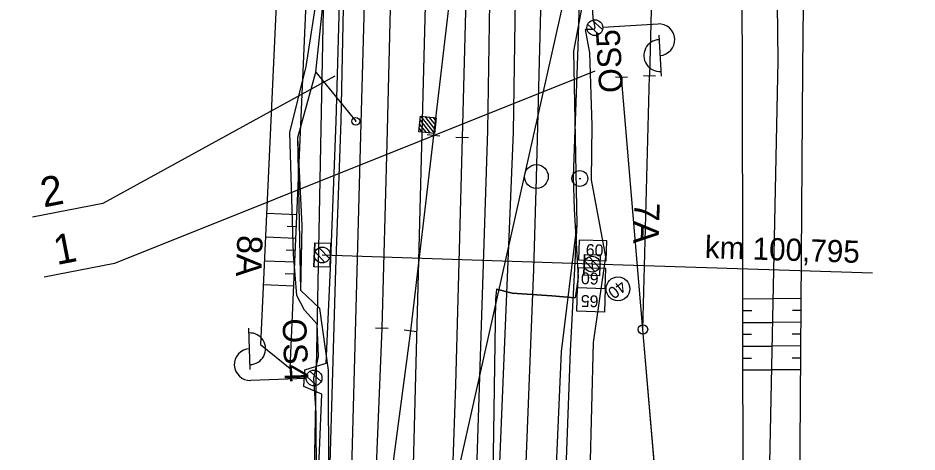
# Model space of a CAD drawing. Extents: x -545736 to -544888, y -1122892 to -1119128.
# Drawn here: x -545156.9 to -545100.2, y -1122572.7 to -1122545.3 of the extents above; entities that cross this region are included whole.
import ezdxf

# ---------------------------------------------------------------- set-up
doc = ezdxf.new("R2010")
doc.units = 0
for name, color, linetype in [('osvětlené plochy-hodnota-obrys', 7, 'Continuous'), ('so180602', 7, 'Continuous'), ('Vrstva 1', 7, 'Continuous'), ('Vrstva 1 - Koleje', 7, 'Continuous'), ('Vrstva 11 - Trakce', 7, 'Continuous'), ('Vrstva 12 - Trakce zaklady', 7, 'Continuous'), ('Vrstva 19 - Staniceni', 7, 'Continuous'), ('Vrstva 2', 7, 'Continuous'), ('Vrstva 2 - Vyhybky', 7, 'Continuous'), ('Vrstva 25', 7, 'Continuous'), ('Vrstva 26', 7, 'Continuous'), ('Vrstva 27', 7, 'Continuous'), ('Vrstva 28 - zabzar', 7, 'Continuous'), ('Vrstva 3 - Lisy - Pocitaci body', 7, 'Continuous'), ('Vrstva 31', 7, 'Continuous'), ('Vrstva 32', 7, 'Continuous'), ('Vrstva 35', 7, 'Continuous'), ('Vrstva 4 - Teren - stezky - prechody - plochy', 7, 'Continuous'), ('Vrstva 44', 7, 'Continuous'), ('Vrstva 48', 7, 'Continuous'), ('Vrstva 49', 7, 'Continuous'), ('Vrstva 5 - Vystroj', 7, 'Continuous'), ('Vrstva 63', 7, 'Continuous'), ('Vrstva 7 - Namezniky-vystroj', 7, 'Continuous')]:
    doc.layers.add(name, color=color, linetype=linetype)

msp = doc.modelspace()

# ---------------------------------------------------------------- linework, layer by layer
at = {"layer": 'osvětlené plochy-hodnota-obrys'}
for points in [[(-545134.488, -1122383.09), (-545138.436, -1122585.69), (-545142.696, -1122618.23), (-545150.566, -1122647.812), (-545144.37, -1122649.678)], [(-545136.491, -1122623.942), (-545134.432, -1122610.076), (-545134.432, -1122610.076), (-545130.588, -1122580.54), (-545121.507, -1122539.928), (-545114.985, -1122440.379), (-545107.655, -1122408.436), (-545092.05, -1122405.326)]]:
    msp.add_lwpolyline(points, dxfattribs=at)
at = {"layer": 'Vrstva 1'}
msp.add_line((-545117.455, -1122564.946), (-545117.039, -1122548.942), dxfattribs=at)
for points in [[(-545115.56, -1122488.812), (-545115.616, -1122491.209), (-545116.093, -1122511.333), (-545117.039, -1122548.942)], [(-545116.598, -1122574.975), (-545117.455, -1122564.946), (-545118.815, -1122549.016)]]:
    msp.add_lwpolyline(points, dxfattribs=at)
at = {"layer": 'Vrstva 1 - Koleje'}
for points in [[(-545127.491, -1122606.436), (-545126.409, -1122596.831), (-545125.507, -1122585.879), (-545124.881, -1122574.98), (-545124.42, -1122563.223), (-545124.354, -1122561.161), (-545124.185, -1122555.363), (-545123.884, -1122543.958), (-545123.736, -1122538.389), (-545123.69, -1122536.639), (-545123.368, -1122524.352), (-545123.06, -1122512.551), (-545122.825, -1122503.596), (-545122.749, -1122500.723), (-545122.248, -1122481.529), (-545122.227, -1122480.729)], [(-545132.113, -1122493.06), (-545132.351, -1122502.539), (-545132.576, -1122511.557), (-545132.791, -1122520.224), (-545133.022, -1122529.75), (-545133.182, -1122536.046), (-545133.362, -1122542.952), (-545133.631, -1122553.198), (-545133.835, -1122560.954), (-545133.937, -1122564.862), (-545134.77, -1122584.848), (-545135.963, -1122597.599), (-545136.038, -1122598.395)], [(-545128.351, -1122532.879), (-545128.372, -1122533.679), (-545128.87, -1122552.83), (-545129.057, -1122559.925), (-545129.288, -1122568.437), (-545129.604, -1122577.497), (-545129.925, -1122584.285), (-545130.831, -1122596.948), (-545132.201, -1122608.983), (-545133.84, -1122619.134), (-545136.174, -1122630.305), (-545137.455, -1122635.497), (-545140.817, -1122647.245), (-545144.325, -1122657.562), (-545148.206, -1122667.467), (-545152.577, -1122677.284), (-545157.303, -1122686.734), (-545161.121, -1122693.673), (-545165.852, -1122701.579), (-545166.19, -1122702.117), (-545166.476, -1122702.566), (-545172.093, -1122711.045)], [(-545128.351, -1122532.879), (-545128.444, -1122533.674), (-545130.677, -1122552.693), (-545132.131, -1122565.025), (-545134.77, -1122584.848), (-545135.963, -1122597.599), (-545136.038, -1122598.395)]]:
    msp.add_lwpolyline(points, dxfattribs=at)
at = {"layer": 'Vrstva 11 - Trakce'}
for p, q in [((-545137.534, -1122560.711), (-545138.158, -1122560.044)), ((-545137.255, -1122560.46), (-545137.888, -1122559.783)), ((-545120.658, -1122560.825), (-545137.702, -1122560.244)), ((-545120.489, -1122561.292), (-545121.114, -1122560.625)), ((-545120.211, -1122561.041), (-545120.844, -1122560.365))]:
    msp.add_line(p, q, dxfattribs=at)
for centre in [(-545137.702, -1122560.244), (-545120.658, -1122560.825)]:
    msp.add_circle(centre, 0.5, dxfattribs=at)
at = {"layer": 'Vrstva 12 - Trakce zaklady'}
for p, q in [((-545138.173, -1122559.467), (-545137.174, -1122559.501)), ((-545121.148, -1122560.204), (-545120.149, -1122560.237)), ((-545137.225, -1122561.014), (-545138.224, -1122560.98)), ((-545120.193, -1122561.56), (-545121.192, -1122561.527))]:
    msp.add_line(p, q, dxfattribs=at)
for points in [[(-545137.174, -1122559.501), (-545137.225, -1122561.014), (-545138.224, -1122560.98), (-545138.173, -1122559.467), (-545137.174, -1122559.501)], [(-545138.173, -1122559.467), (-545138.173, -1122559.467), (-545138.224, -1122560.98), (-545138.224, -1122560.98)], [(-545137.174, -1122559.501), (-545137.174, -1122559.501), (-545137.225, -1122561.014), (-545137.225, -1122561.014)], [(-545121.192, -1122561.527), (-545121.148, -1122560.204), (-545120.149, -1122560.237), (-545120.193, -1122561.56), (-545121.192, -1122561.527)], [(-545121.148, -1122560.204), (-545121.148, -1122560.204), (-545121.192, -1122561.527), (-545121.192, -1122561.527)], [(-545120.149, -1122560.237), (-545120.149, -1122560.237), (-545120.193, -1122561.56), (-545120.193, -1122561.56)]]:
    msp.add_lwpolyline(points, dxfattribs=at)
at = {"layer": 'Vrstva 19 - Staniceni'}
msp.add_circle((-545124.183, -1122555.287), 0.75, dxfattribs=at)
at = {"layer": 'Vrstva 2'}
for p, q in [((-545118.44, -1122549.026), (-545119.19, -1122549.006)), ((-545117.455, -1122564.946), (-545117.039, -1122548.942)), ((-545116.664, -1122548.952), (-545117.414, -1122548.932))]:
    msp.add_line(p, q, dxfattribs=at)
msp.add_lwpolyline([(-545116.598, -1122574.975), (-545116.655, -1122574.287), (-545117.455, -1122564.946), (-545118.815, -1122549.016)], dxfattribs=at)
msp.add_circle((-545117.455, -1122564.946), 0.3, dxfattribs=at)
at = {"layer": 'Vrstva 2 - Vyhybky'}
for p, q in [((-545130.28, -1122552.74), (-545131.074, -1122552.646)), ((-545128.47, -1122552.841), (-545129.27, -1122552.819)), ((-545134.337, -1122564.852), (-545133.537, -1122564.872)), ((-545132.528, -1122564.978), (-545131.734, -1122565.072))]:
    msp.add_line(p, q, dxfattribs=at)
for points in [[(-545126.015, -1122512.98), (-545128.258, -1122532.085), (-545128.351, -1122532.879), (-545128.444, -1122533.674), (-545130.677, -1122552.693)], [(-545127.83, -1122512.852), (-545128.33, -1122532.079), (-545128.351, -1122532.879), (-545128.372, -1122533.679), (-545128.87, -1122552.83)], [(-545132.131, -1122565.025), (-545134.77, -1122584.848), (-545135.963, -1122597.599), (-545136.038, -1122598.395)], [(-545133.937, -1122564.862), (-545134.77, -1122584.848)]]:
    msp.add_lwpolyline(points, dxfattribs=at)
at = {"layer": 'Vrstva 25'}
for p, q in [((-545120.945, -1122545.671), (-545120.23, -1122546.307)), ((-545120.669, -1122545.415), (-545120.011, -1122546)), ((-545119.996, -1122545.855), (-545116.502, -1122545.649)), ((-545116.461, -1122546.348), (-545116.308, -1122548.943)), ((-545142.244, -1122567.466), (-545142.342, -1122564.868)), ((-545138.72, -1122568.033), (-545142.217, -1122568.166)), ((-545138.056, -1122568.486), (-545138.701, -1122567.888)), ((-545137.774, -1122568.236), (-545138.476, -1122567.585))]:
    msp.add_line(p, q, dxfattribs=at)
for centre in [(-545120.495, -1122545.884), (-545120.495, -1122545.884), (-545138.22, -1122568.014), (-545138.22, -1122568.014)]:
    msp.add_circle(centre, 0.5, dxfattribs=at)
for centre, start, end in [((-545116.443, -1122546.647), 273.3665, 93.3665), ((-545116.397, -1122547.646), 92.6639, 274.069), ((-545142.281, -1122566.167), 271.4722, 92.8773), ((-545142.255, -1122567.167), 92.1747, 272.1747)]:
    msp.add_arc(centre, 1, start, end, dxfattribs=at)
at = {"layer": 'Vrstva 26'}
for points in [[(-545119.68, -1122488.49), (-545120.17, -1122501.15), (-545119.71, -1122502.33), (-545119.7, -1122504.78), (-545119.85, -1122506.31), (-545120.44, -1122510.12), (-545120.81, -1122524.13), (-545121.12, -1122536.77), (-545120.62, -1122545.27), (-545120.495, -1122545.884), (-545120.53, -1122546.01), (-545121.1, -1122546), (-545120.82, -1122547.48), (-545120.68, -1122552.06), (-545120.73, -1122555.49), (-545119.81, -1122560.36), (-545120.59, -1122565.76), (-545120.92, -1122578.15), (-545121.15, -1122584.54), (-545121.23, -1122585.48), (-545121.28, -1122585.86), (-545121.286, -1122586.03)], [(-545138.229, -1122568.031), (-545137.937, -1122566.657), (-545138.015, -1122564.603), (-545138.832, -1122563.727), (-545139.297, -1122562.807), (-545139.509, -1122560.192), (-545139.746, -1122552.512), (-545138.721, -1122548.343), (-545137.938, -1122543.312), (-545136.85, -1122534.793), (-545136.864, -1122531.996), (-545136.831, -1122528.647), (-545137.221, -1122526.243), (-545137.59, -1122523.973), (-545137.332, -1122522.241), (-545137.098, -1122519.747), (-545136.605, -1122518.752), (-545136.193, -1122512.982), (-545134.952, -1122511.155), (-545134.594, -1122508.496), (-545134.254, -1122496.631)], [(-545140.173, -1122601.416), (-545139.225, -1122598.674), (-545138.828, -1122595.457), (-545138.236, -1122588.391), (-545138.033, -1122583.268), (-545138.077, -1122570.236), (-545138.229, -1122568.031), (-545138.22, -1122568.014)]]:
    msp.add_lwpolyline(points, dxfattribs=at)
at = {"layer": 'Vrstva 27'}
msp.add_line((-545135.581, -1122551.825), (-545135.579, -1122551.775), dxfattribs=at)
msp.add_circle((-545135.58, -1122551.8), 0.25, dxfattribs=at)
at = {"layer": 'Vrstva 28 - zabzar'}
msp.add_line((-545138.1, -1122548.7), (-545135.58, -1122551.8), dxfattribs=at)
for points in [[(-545139.49, -1122604.09), (-545138.69, -1122597.74), (-545138.27, -1122594.46), (-545137.55, -1122584.26), (-545137.29, -1122574.56), (-545137.31, -1122567.52), (-545137.85, -1122563.63), (-545139.06, -1122562.49), (-545138.96, -1122558.39), (-545139.24, -1122552.83), (-545138.1, -1122548.7), (-545137.31, -1122541.08), (-545136.56, -1122536.26), (-545136.54, -1122531.79), (-545136.53, -1122525.43), (-545137.3, -1122521.01), (-545137.26, -1122503.3), (-545136.84, -1122494.09)], [(-545120.32, -1122497.45), (-545120.28, -1122501.2), (-545119.86, -1122502.26), (-545120.03, -1122503.25), (-545120.08, -1122505.06), (-545120.41, -1122515.25), (-545120.88, -1122524.03), (-545121.29, -1122538.53), (-545121.33, -1122539.85), (-545121.51, -1122544.9), (-545121.56, -1122547.09), (-545121.86, -1122555.28), (-545121.79, -1122557.35), (-545121.55, -1122561.65), (-545121.74, -1122562.94), (-545123.21, -1122562.82), (-545125.72, -1122562.65), (-545126.7, -1122562.41), (-545126.77, -1122563.06), (-545126.93, -1122574.21), (-545127.34, -1122580.8), (-545127.46, -1122581.87)]]:
    msp.add_lwpolyline(points, dxfattribs=at)
at = {"layer": 'Vrstva 3 - Lisy - Pocitaci body'}
for p, q in [((-545131.495, -1122551.467), (-545130.618, -1122552.577)), ((-545131.232, -1122551.498), (-545130.587, -1122552.313)), ((-545130.968, -1122551.529), (-545130.556, -1122552.05)), ((-545130.705, -1122551.56), (-545130.526, -1122551.787)), ((-545131.557, -1122551.994), (-545131.145, -1122552.515)), ((-545131.526, -1122551.73), (-545130.881, -1122552.546)), ((-545131.588, -1122552.257), (-545131.408, -1122552.484))]:
    msp.add_line(p, q, dxfattribs=at)
msp.add_lwpolyline([(-545130.502, -1122551.583), (-545130.618, -1122552.577), (-545131.611, -1122552.46), (-545131.495, -1122551.467)], close=True, dxfattribs=at)
at = {"layer": 'Vrstva 31'}
msp.add_lwpolyline([(-545139.49, -1122604.09), (-545138.69, -1122597.74), (-545138.27, -1122594.46), (-545137.55, -1122584.26), (-545137.29, -1122574.56), (-545137.31, -1122567.52), (-545137.85, -1122563.63), (-545139.06, -1122562.49), (-545139.24, -1122552.83), (-545138.1, -1122548.7), (-545137.31, -1122541.08), (-545136.56, -1122536.26), (-545136.53, -1122525.43), (-545137.3, -1122521.01), (-545137.26, -1122503.3), (-545136.84, -1122494.09)], dxfattribs=at)
at = {"layer": 'Vrstva 32'}
msp.add_lwpolyline([(-545139.49, -1122604.09), (-545138.2, -1122600.33), (-545138.01, -1122598.42), (-545138.69, -1122597.74), (-545138.27, -1122594.46), (-545137.55, -1122584.26), (-545137.29, -1122574.56), (-545137.31, -1122567.52), (-545137.85, -1122563.63), (-545139.06, -1122562.49), (-545138.96, -1122558.39), (-545139.24, -1122552.83), (-545138.1, -1122548.7), (-545137.31, -1122541.08), (-545136.56, -1122536.26), (-545136.53, -1122525.43), (-545137.3, -1122521.01), (-545137.26, -1122503.3), (-545136.84, -1122494.09)], dxfattribs=at)
msp.add_lwpolyline([(-545139.49, -1122604.09), (-545138.2, -1122600.33), (-545138.01, -1122598.42), (-545138.69, -1122597.74), (-545138.27, -1122594.46), (-545137.55, -1122584.26), (-545137.29, -1122574.56), (-545137.31, -1122567.52), (-545137.85, -1122563.63), (-545139.06, -1122562.49), (-545138.96, -1122558.39), (-545139.24, -1122552.83), (-545138.1, -1122548.7), (-545137.31, -1122541.08), (-545136.56, -1122536.26), (-545136.53, -1122525.43), (-545137.3, -1122521.01), (-545137.26, -1122503.3), (-545136.84, -1122494.09)], dxfattribs=at)
at = {"layer": 'Vrstva 35'}
msp.add_lwpolyline([(-545126.7, -1122562.41), (-545125.72, -1122562.65), (-545123.21, -1122562.82), (-545121.74, -1122562.94)], dxfattribs=at)
at = {"layer": 'Vrstva 4 - Teren - stezky - prechody - plochy'}
for points in [[(-545191.629, -1122723.588), (-545190.606, -1122724.4), (-545183.082, -1122715.247), (-545174.471, -1122703.078), (-545169.188, -1122694.668), (-545163.388, -1122684.3), (-545157.763, -1122672.946), (-545152.235, -1122660.118), (-545147.809, -1122647.698), (-545144.117, -1122635.247), (-545141.561, -1122624.265), (-545139.354, -1122611.942), (-545137.55, -1122598.304), (-545138.381, -1122598.177), (-545138.144, -1122596.165), (-545137.394, -1122596.23), (-545137.164, -1122594.37), (-545136.011, -1122579.974), (-545135.245, -1122551.924), (-545134.376, -1122521.14), (-545133.892, -1122501.709), (-545133.405, -1122481.658)], [(-545140.685, -1122611.253), (-545138.752, -1122594.386), (-545137.402, -1122579.893), (-545136.844, -1122561.129), (-545136.511, -1122551.767), (-545135.87, -1122521.211), (-545135.812, -1122519.734), (-545135.589, -1122501.439), (-545134.927, -1122481.492), (-545133.405, -1122481.658)], [(-545126.359, -1122615.637), (-545123.475, -1122595.334), (-545122.576, -1122581.189), (-545122.024, -1122566.306), (-545121.598, -1122558.297), (-545121.821, -1122547.368), (-545120.582, -1122540.764), (-545120.053, -1122538.008), (-545120.048, -1122536.451), (-545120.424, -1122535.984), (-545120.015, -1122521.738), (-545120.268, -1122521.539), (-545120.287, -1122519.886), (-545120.045, -1122519.696), (-545119.214, -1122493.259)], [(-545141.024, -1122611.09), (-545139.933, -1122602.085), (-545139.716, -1122601.069), (-545140.128, -1122600.945), (-545139.688, -1122595.933), (-545139.138, -1122595.855), (-545139.019, -1122594.44), (-545139.197, -1122594.314), (-545138.162, -1122579.754), (-545137.734, -1122569.04), (-545138.855, -1122568.556), (-545138.807, -1122567.496), (-545137.462, -1122567.077), (-545137.179, -1122561.067), (-545136.824, -1122551.814), (-545135.969, -1122521.336), (-545135.87, -1122521.211), (-545135.812, -1122519.734), (-545135.964, -1122519.738), (-545135.589, -1122501.439), (-545135.812, -1122519.734)], [(-545143.646, -1122627.169), (-545143.029, -1122623.952), (-545140.685, -1122611.253), (-545138.752, -1122594.386), (-545137.402, -1122579.893), (-545136.844, -1122561.129), (-545136.511, -1122551.767), (-545135.87, -1122521.211)], [(-545128.182, -1122580.908), (-545127.25, -1122552.375), (-545127.114, -1122544.286), (-545126.59, -1122534.029), (-545125.795, -1122523.347), (-545124.869, -1122523.395)], [(-545128.182, -1122580.908), (-545126.797, -1122581.016), (-545125.631, -1122552.485), (-545125.511, -1122544.056), (-545125.16, -1122533.938), (-545124.869, -1122523.395)], [(-545183.417, -1122735.539), (-545172.736, -1122722.592), (-545164.193, -1122710.6), (-545158.368, -1122701.539), (-545152.26, -1122690.517), (-545146.06, -1122678.085), (-545140.529, -1122664.937), (-545135.605, -1122651.492), (-545131.928, -1122638.755), (-545129.164, -1122627.095), (-545126.823, -1122615.114), (-545124.297, -1122595.163), (-545123.247, -1122581.223), (-545122.607, -1122566.342), (-545121.598, -1122558.297)]]:
    msp.add_lwpolyline(points, dxfattribs=at)
at = {"layer": 'Vrstva 44'}
msp.add_lwpolyline([(-545133.427, -1122599.241), (-545132.083, -1122579.16), (-545130.845, -1122531.562), (-545130.119, -1122502.202), (-545130.021, -1122501.998), (-545129.768, -1122502.059), (-545120.639, -1122502.325), (-545120.437, -1122502.27), (-545120.505, -1122501.979), (-545119.331, -1122472.539), (-545116.186, -1122445.902), (-545109.415, -1122409.043)], dxfattribs=at)
at = {"layer": 'Vrstva 48'}
for p, q in [((-545139.304, -1122557.709), (-545141.21, -1122557.627)), ((-545139.336, -1122558.458), (-545139.909, -1122558.434)), ((-545139.369, -1122559.208), (-545141.279, -1122559.125)), ((-545139.401, -1122559.957), (-545139.975, -1122559.932)), ((-545139.433, -1122560.706), (-545141.348, -1122560.624)), ((-545139.466, -1122561.456), (-545140.041, -1122561.431)), ((-545139.498, -1122562.205), (-545141.417, -1122562.122)), ((-545111.15, -1122563.003), (-545109.252, -1122563)), ((-545107.459, -1122563.003), (-545109.252, -1122562.99)), ((-545111.149, -1122563.753), (-545110.584, -1122563.752)), ((-545107.465, -1122563.753), (-545108.005, -1122563.749)), ((-545111.147, -1122564.503), (-545109.284, -1122564.5)), ((-545107.47, -1122564.503), (-545109.283, -1122564.489)), ((-545111.146, -1122565.253), (-545110.592, -1122565.252)), ((-545107.476, -1122565.253), (-545108.023, -1122565.249)), ((-545111.145, -1122566.003), (-545109.315, -1122566)), ((-545107.481, -1122566.003), (-545109.315, -1122565.989)), ((-545111.143, -1122566.753), (-545110.6, -1122566.752)), ((-545107.487, -1122566.753), (-545108.04, -1122566.749)), ((-545111.142, -1122567.503), (-545109.347, -1122567.5)), ((-545107.493, -1122567.503), (-545109.347, -1122567.489))]:
    msp.add_line(p, q, dxfattribs=at)
at = {"layer": 'Vrstva 49'}
for points in [[(-545113.495, -1122581.411), (-545112.777, -1122581.971), (-545111.538, -1122582.022), (-545111.113, -1122581.533), (-545111.39, -1122579.822), (-545111.125, -1122576.998), (-545111.177, -1122547.82), (-545111.31, -1122527.082), (-545110.885, -1122513.233), (-545111.712, -1122499.521), (-545111.022, -1122494.77), (-545111.276, -1122489.851), (-545112.466, -1122485.765), (-545113.508, -1122481.172), (-545118.56, -1122480.386), (-545116.295, -1122478.192), (-545114.105, -1122467.739)], [(-545114.105, -1122467.739), (-545114.075, -1122477.033), (-545110.879, -1122479.392), (-545108.472, -1122487.18), (-545109.029, -1122489.664), (-545108.629, -1122493.778), (-545109.142, -1122499.766), (-545109.023, -1122514.339), (-545109.19, -1122526.527), (-545108.935, -1122547.978), (-545109.536, -1122576.466), (-545109.517, -1122580.577), (-545110.186, -1122583.065), (-545111.223, -1122583.154), (-545113.352, -1122583.617)], [(-545113.139, -1122585.24), (-545111.088, -1122584.495), (-545108.725, -1122584.097), (-545107.845, -1122579.6), (-545107.551, -1122575.308), (-545107.35, -1122548.456), (-545107.124, -1122526.449), (-545107.688, -1122515.242), (-545107.207, -1122499.955), (-545108.629, -1122493.778)], [(-545140.592, -1122508.123), (-545140.363, -1122520.307), (-545141.282, -1122531.19), (-545140.602, -1122544.441), (-545141.591, -1122565.886), (-545139.722, -1122567.402)], [(-545139.722, -1122567.402), (-545138.726, -1122544.307), (-545138.682, -1122531.367), (-545138.904, -1122520.406), (-545139.428, -1122509.283), (-545140.592, -1122508.123)]]:
    msp.add_lwpolyline(points, dxfattribs=at)
at = {"layer": 'Vrstva 5 - Vystroj'}
for p, q in [((-545120.658, -1122560.825), (-545120.65, -1122560.575)), ((-545120.658, -1122560.825), (-545120.666, -1122561.075)), ((-545102.954, -1122561.392), (-545120.658, -1122560.825))]:
    msp.add_line(p, q, dxfattribs=at)
for points in [[(-545121.525, -1122560.547), (-545119.775, -1122560.603), (-545119.735, -1122559.354), (-545121.485, -1122559.298)], [(-545119.791, -1122561.103), (-545121.541, -1122561.047), (-545121.581, -1122562.296), (-545119.831, -1122562.352)], [(-545121.581, -1122562.296), (-545119.831, -1122562.352), (-545119.879, -1122563.851), (-545121.629, -1122563.795)]]:
    msp.add_lwpolyline(points, close=True, dxfattribs=at)
msp.add_circle((-545119.032, -1122562.38), 0.75, dxfattribs=at)
at = {"layer": 'Vrstva 63'}
for p, q in [((-545120.487, -1122548.622), (-545150.812, -1122560.788)), ((-545136.914, -1122548.951), (-545151.554, -1122556.996)), ((-545151.554, -1122556.996), (-545155.998, -1122557.861)), ((-545150.812, -1122560.788), (-545155.256, -1122561.652))]:
    msp.add_line(p, q, dxfattribs=at)
at = {"layer": 'Vrstva 7 - Namezniky-vystroj'}
msp.add_line((-545121.485, -1122555.411), (-545121.385, -1122555.411), dxfattribs=at)
msp.add_circle((-545121.435, -1122555.411), 0.5, dxfattribs=at)

# ---------------------------------------------------------------- texts
at = {"layer": 'so180602'}
for s, p in [('2', (-545155.292, -1122557.247)), ('1', (-545154.469, -1122560.883))]:
    msp.add_text(s, height=1.875, rotation=10.9955, dxfattribs=at).set_placement(p)
at = {"layer": 'Vrstva 11 - Trakce'}
for s, rotation, p in [('7A', 268.0952, (-545117.987, -1122556.895)), ('8A', 268.0694, (-545143.06, -1122558.97))]:
    msp.add_text(s, height=1.6, rotation=rotation, dxfattribs=at).set_placement(p)
at = {"layer": 'Vrstva 25'}
for s, rotation, p in [('OS5', 93.3665, (-545118.702, -1122549.961)), ('OS4', 272.1747, (-545140.218, -1122564.28))]:
    msp.add_text(s, height=1.5, rotation=rotation, dxfattribs=at).set_placement(p)
at = {"layer": 'Vrstva 5 - Vystroj'}
for s, height, rotation, p in [('km 100,795', 1.4, 358.1667, (-545113.563, -1122560.432)), ('60', 0.75, 358.1667, (-545121.075, -1122560.294)), ('60', 0.75, 178.1667, (-545120.24, -1122561.369)), ('40', 0.75, 217.7648, (-545118.863, -1122561.792)), ('65', 0.75, 178.1667, (-545120.251, -1122562.801))]:
    msp.add_text(s, height=height, rotation=rotation, dxfattribs=at).set_placement(p)

doc.saveas('drawing.dxf')
